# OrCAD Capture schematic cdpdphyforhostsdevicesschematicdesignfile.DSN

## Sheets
1 2 History_Sheet: title: Revision History; rev: 1.3
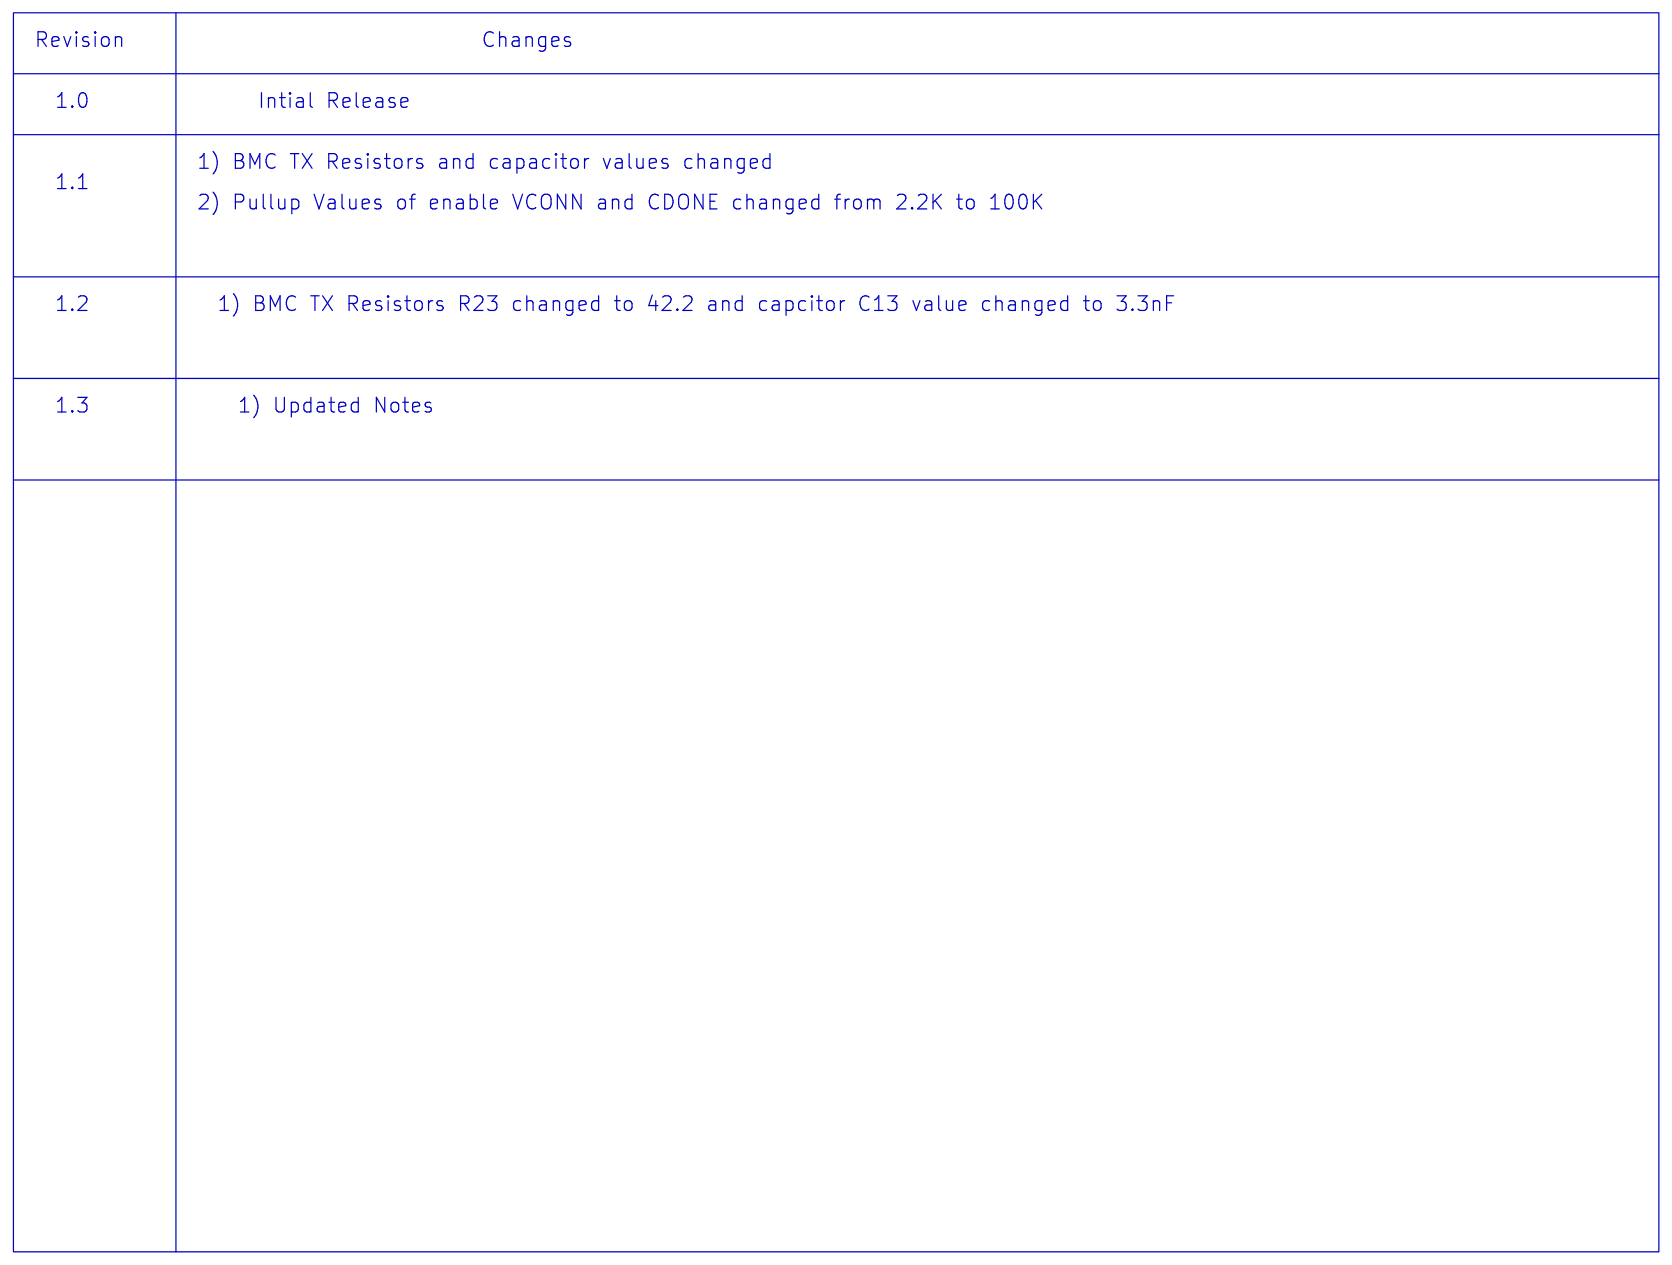
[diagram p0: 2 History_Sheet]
2 1 CD_PD_PHY_Hosts_Devices: size B; title: CD_PD_PHY_Hosts_Devices
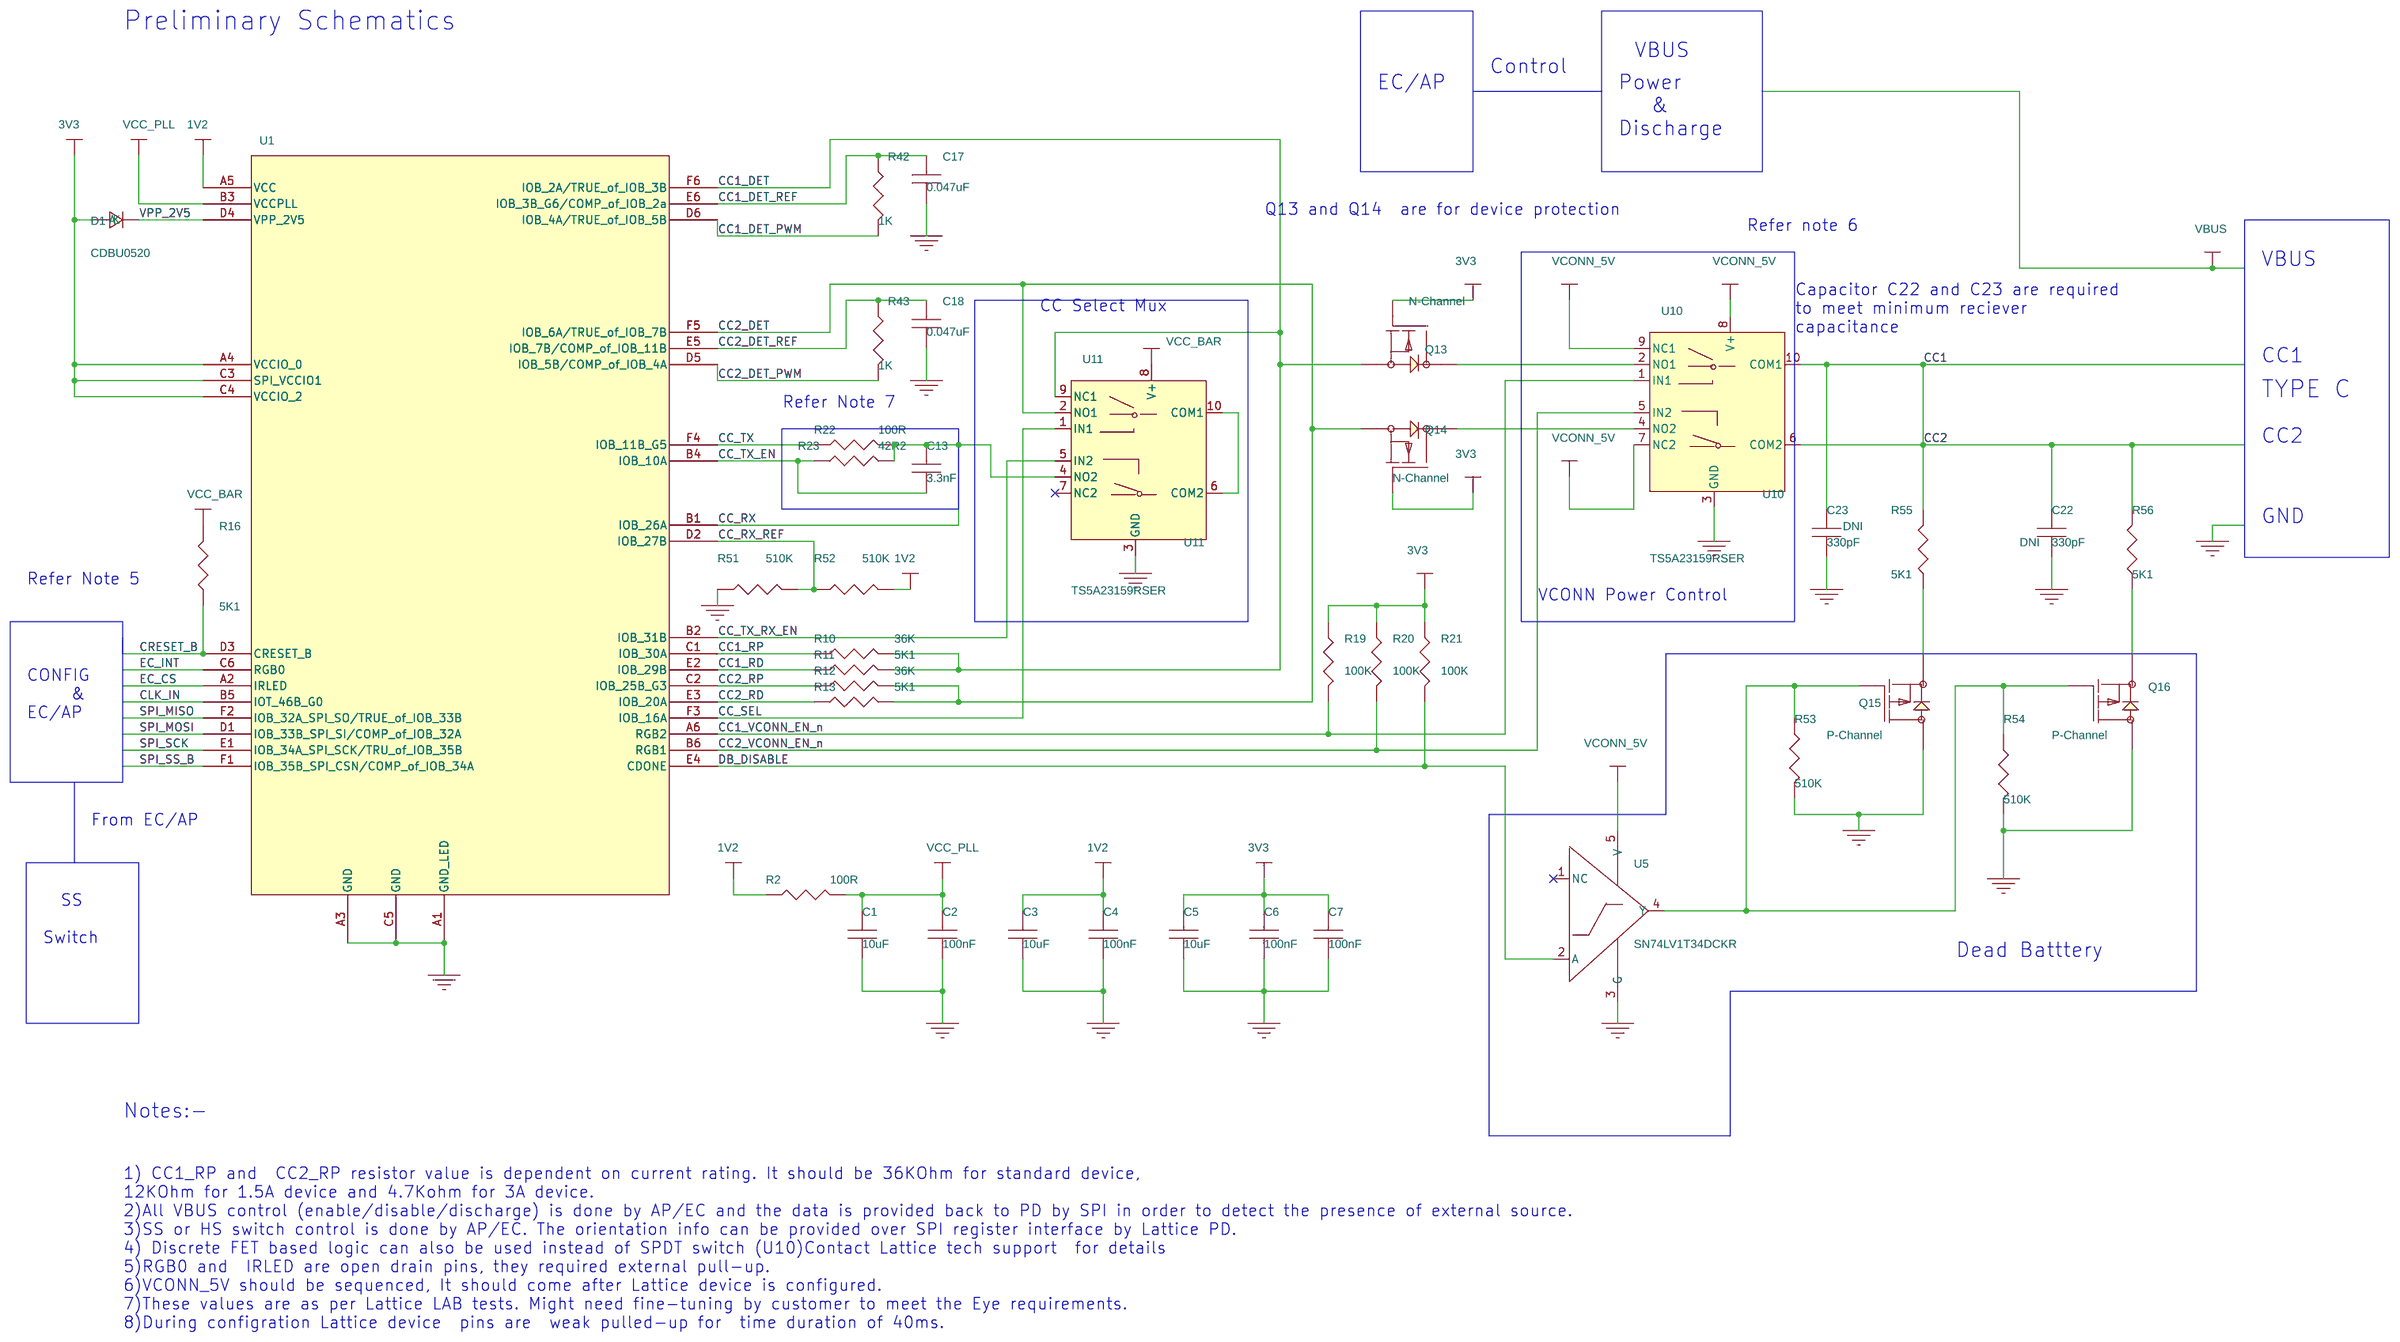
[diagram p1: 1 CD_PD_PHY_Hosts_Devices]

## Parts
C1  10uF  [C0805]
C2  100nF  [C0402]
C3  10uF  [C0805]
C4  100nF  [C0402]
C5  10uF  [C0805]
C6  100nF  [C0402]
C7  100nF  [C0402]
C13  3.3nF  [C0402]
C17  0.047uF  [C0402]
C18  0.047uF  [C0402]
C22  330pF  [C0402]
C23  330pF  [C0402]
D1  CDBU0520  [D0603]
Q13  N-Channel  [BSH103,235]
Q14  N-Channel  [BSH103,235]
Q15  P-Channel  [NTA4151PT1G_SOT416]
Q16  P-Channel  [NTA4151PT1G_SOT416]
R2  100R  [R0402]
R10  36K  [R0402]
R11  5K1  [R0402]
R12  36K  [R0402]
R13  5K1  [R0402]
R16  5K1  [R0402]
R19  100K  [R0402]
R20  100K  [R0402]
R21  100K  [R0402]
R22  100R  [R0402]
R23  42R2  [R0402]
R42  1K  [R0402]
R43  1K  [R0402]
R51  510K  [R0603]
R52  510K  [R0603]
R53  510K  [R0603]
R54  510K  [R0603]
R55  5K1  [R0402]
R56  5K1  [R0402]
U1  ICE5LP4K
U5  SN74LV1T34DCKR  [SC-70-5]
U10  TS5A23159RSER  [TS5A23159_10UQFN]
U11  TS5A23159RSER  [TS5A23159_10UQFN]

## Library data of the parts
C1 C3 C5 = CAP_CER_10uF_0805_10V
C2 C4 C6 C7 = CAP_CER_100nF_0402_10V
C13 = CAP_CER_3.3nF_0402_10V
C17 C18 = CAP_CER_0.047uF_0402_10V
C22 C23 = CAP_CER_330pF_0402_16V: BOM_Note: DNI
D1 = DIODE_SCHOTTKY_20V_0603
Q13 Q14 = MOSFET_N-CHAN-0P45V_1
Q15 Q16 = MOSFET_P-CHAN-0P45_0P76A
R2 = RES_100R_1W16_0402_5P
R10 R12 = RES_36K_1W16_0402_5P
R11 R13 R16 R55 R56 = RES_5K1_1W16_0402_5P
R19-R21 = RES_100K_1W16_0402_5P
R22 = RES_100R_1W16_0402_1P
R23 = RES_42R_1W16_0402_1P
R42 R43 = RES_1K_1W16_0402_5P
R51-R54 = RES_500K_1W16_0402_5P
U1 = ICE5LP4K_8
U5 = VLT_BUFF_SC70_NEW
U10 U11 = SPDT_DUAL_0

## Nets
1V2: C3.1 C4.1 R2.1 R52.2 U1.A5(VCC)
3V3: C5.1 C6.1 C7.1 D1.1(A) Q13.1(G) Q14.1(G) R16.2 R19.1 R20.1 R21.1 U1.A4(VCCIO_0) U1.C3(SPI_VCCIO1) U1.C4(VCCIO_2) U11.8(V+)
GND: C1.2 C2.2 C3.2 C4.2 C5.2 C6.2 C7.2 C17.2 C18.2 C22.2 C23.2 Q15.3(D) Q16.3(D) R51.1 R53.2 R54.2 U1.A1(GND_LED) U1.A3(GND) U1.C5(GND) U5.3(G) U10.3(GND) U11.3(GND)
VCC_PLL: C1.1 C2.1 R2.2 U1.B3(VCCPLL)
CC1: C23.1 R55.2 U10.10(COM1)
CC1_DET: Q13.2(S) R10.2 R11.2 U1.F6(IOB_2A/TRUE_of_IOB_3B) U11.9(NC1)
CC1_DET_PWM: R42.2 U1.D6(IOB_4A/TRUE_of_IOB_5B)
CC1_DET_REF: C17.1 R42.1 U1.E6(IOB_3B_G6/COMP_of_IOB_2a)
CC1_RD: R11.1 U1.E2(IOB_29B)
CC1_RP: R10.1 U1.C1(IOB_30A)
CC1_VCONN_EN_n: R19.2 U1.A6(RGB2) U10.1(IN1)
CC2: C22.1 R56.2 U10.6(COM2)
CC2_DET: Q14.2(S) R12.2 R13.2 U1.F5(IOB_6A/TRUE_of_IOB_7B) U11.2(NO1)
CC2_DET_PWM: R43.2 U1.D5(IOB_5B/COMP_of_IOB_4A)
CC2_DET_REF: C18.1 R43.1 U1.E5(IOB_7B/COMP_of_IOB_11B)
CC2_RD: R13.1 U1.E3(IOB_20A)
CC2_RP: R12.1 U1.C2(IOB_25B_G3)
CC2_VCONN_EN_n: R20.2 U1.B6(RGB1) U10.5(IN2)
CC_RX: C13.1 R22.2 R23.2 U1.B1(IOB_26A) U11.4(NO2)
CC_RX_REF: R51.2 R52.1 U1.D2(IOB_27B)
CC_SEL: U1.F3(IOB_16A) U11.1(IN1)
CC_TX: R22.1 U1.F4(IOB_11B_G5)
CC_TX_EN: C13.2 R23.1 U1.B4(IOB_10A)
CC_TX_RX_EN: U1.B2(IOB_31B) U11.5(IN2)
CLK_IN: U1.B5(IOT_46B_G0)
CRESET_B: R16.1 U1.D3(CRESET_B)
DB_DISABLE: R21.2 U1.E4(CDONE) U5.2(A)
EC_CS: U1.A2(IRLED)
EC_INT: U1.C6(RGB0)
SPI_MISO: U1.F2(IOB_32A_SPI_SO/TRUE_of_IOB_33B)
SPI_MOSI: U1.D1(IOB_33B_SPI_SI/COMP_of_IOB_32A)
SPI_SCK: U1.E1(IOB_34A_SPI_SCK/TRU_of_IOB_35B)
SPI_SS_B: U1.F1(IOB_35B_SPI_CSN/COMP_of_IOB_34A)
VCONN_5V: U5.5(V) U10.7(NC2) U10.8(V+) U10.9(NC1)
VPP_2V5: D1.2(K) U1.D4(VPP_2V5)
N16786515: Q13.3(D) U10.2(NO1)
N16787685: Q14.3(D) U10.4(NO2)
N16790235: Q15.1(G) Q16.1(G) R53.1 R54.1 U5.4(Y)
N16790516: Q15.2(S) R55.1
N16790569: Q16.2(S) R56.1
N16802402: U11.6(COM2) U11.10(COM1)

Not connected (* = marked no-connect by the designer): U5 1(NC)*; U11 7(NC2)*

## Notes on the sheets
sheet 1
- Revision
- Changes
- 1.0
- Intial Release
- 1) BMC TX Resistors and capacitor values changed
- 1.1
- 2) Pullup Values of enable VCONN and CDONE changed from 2.2K to 100K
- 1.2
- 1) BMC TX Resistors R23 changed to 42.2 and capcitor C13 value changed to 3.3nF
- 1.3
- 1) Updated Notes
sheet 2
- Preliminary Schematics
- VBUS
- EC/AP
- Control
- Power
     &
  Discharge
- Q13 and Q14  are for device protection
- Refer note 6
- VBUS
- Capacitor C22 and C23 are required
  to meet minimum reciever
  capacitance
- CC Select Mux
- CC1
- Refer Note 7
- TYPE C
- CC2
- GND
- Refer Note 5
- VCONN Power Control
- CONFIG
       &
  EC/AP
- From EC/AP
- SS
  Switch
- Dead Batttery
- Notes:-
- 1) CC1_RP and  CC2_RP resistor value is dependent on current rating. It should be 36KOhm for standard device,
  12KOhm for 1.5A device and 4.7Kohm for 3A device.
  2)All VBUS control (enable/disable/discharge) is done by AP/EC and the data is provided back to PD by SPI in order to detect the presence of external source.
  3)SS or HS switch control is done by AP/EC. The orientation info can be provided over SPI register interface by Lattice PD.
  4) Discrete FET based logic can also be used instead of SPDT switch (U10)Contact Lattice tech support  for details
  5)RGB0 and  IRLED are open drain pins, they required external pull-up.
  6)VCONN_5V should be sequenced, It should come after Lattice device is configured.
  7)These values are as per Lattice LAB tests. Might need fine-tuning by customer to meet the Eye requirements.
  8)During configration Lattice device  pins are  weak pulled-up for  time duration of 40ms.
